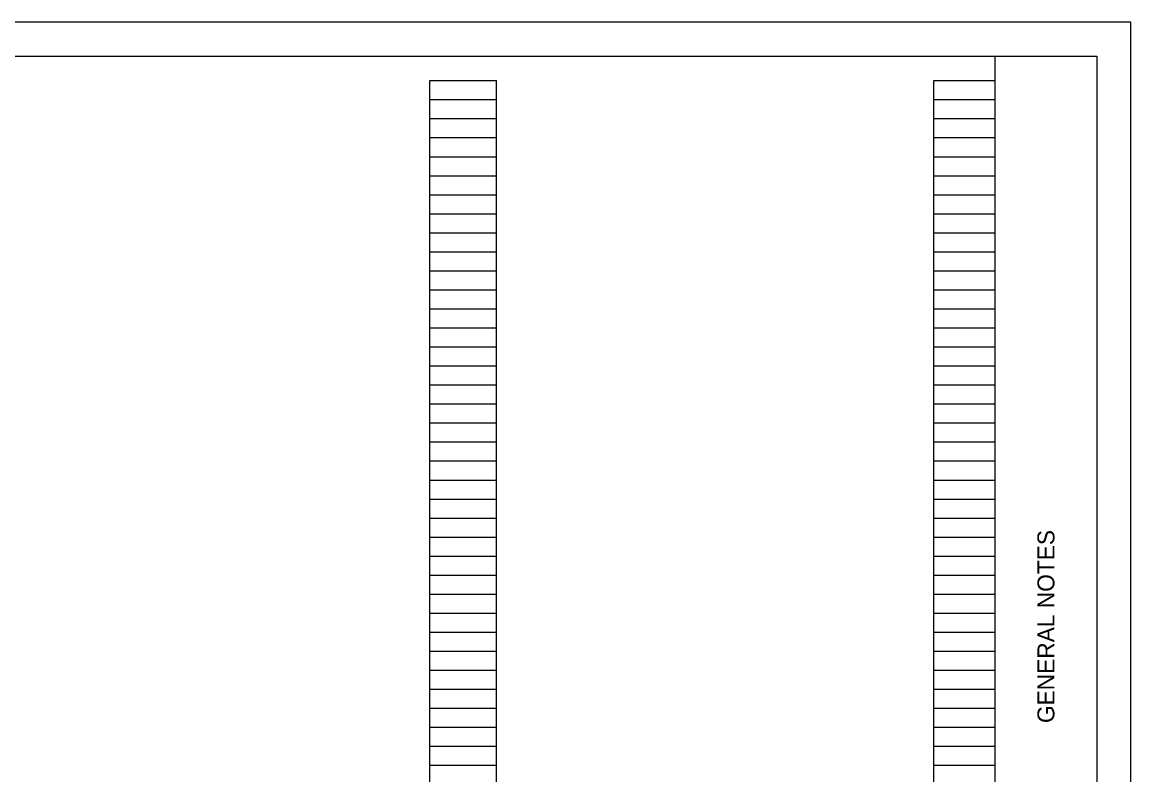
# Model space of a CAD drawing. Extents: x -9.5 to 34, y -6.8 to 28.4.
# Drawn here: x 17.67 to 34, y 10.92 to 22 of the extents above; entities that cross this region are included whole.
import ezdxf

# ---------------------------------------------------------------- set-up
doc = ezdxf.new("R2010")
doc.units = 0
for name, color, linetype in [('PV_P_Drive', 7, 'Continuous'), ('SH_Border', 7, 'Continuous'), ('SH_Cut_Line', 7, 'Continuous'), ('SH_Data', 7, 'Continuous')]:
    doc.layers.add(name, color=color, linetype=linetype)

msp = doc.modelspace()

# ---------------------------------------------------------------- linework, layer by layer
at = {"layer": 'PV_P_Drive'}
for p, q in [((23.68, 0.98), (23.68, 21.14)), ((23.68, 21.14), (24.66, 21.14)), ((24.66, 0.98), (24.66, 21.14)), ((31.1, 0.98), (31.1, 21.14)), ((31.1, 21.14), (32, 21.14)), ((32, 0.98), (32, 21.14)), ((23.68, 20.86), (24.66, 20.86)), ((31.1, 20.86), (32, 20.86)), ((23.68, 20.58), (24.66, 20.58)), ((31.1, 20.58), (32, 20.58)), ((23.68, 20.3), (24.66, 20.3)), ((31.1, 20.3), (32, 20.3)), ((23.68, 20.02), (24.66, 20.02)), ((31.1, 20.02), (32, 20.02)), ((23.68, 19.74), (24.66, 19.74)), ((31.1, 19.74), (32, 19.74)), ((23.68, 19.46), (24.66, 19.46)), ((31.1, 19.46), (32, 19.46)), ((23.68, 19.18), (24.66, 19.18)), ((31.1, 19.18), (32, 19.18)), ((23.68, 18.9), (24.66, 18.9)), ((31.1, 18.9), (32, 18.9)), ((23.68, 18.62), (24.66, 18.62)), ((31.1, 18.62), (32, 18.62)), ((23.68, 18.34), (24.66, 18.34)), ((31.1, 18.34), (32, 18.34)), ((23.68, 18.06), (24.66, 18.06)), ((31.1, 18.06), (32, 18.06)), ((23.68, 17.78), (24.66, 17.78)), ((31.1, 17.78), (32, 17.78)), ((23.68, 17.5), (24.66, 17.5)), ((31.1, 17.5), (32, 17.5)), ((23.68, 17.22), (24.66, 17.22)), ((31.1, 17.22), (32, 17.22)), ((23.68, 16.94), (24.66, 16.94)), ((31.1, 16.94), (32, 16.94)), ((23.68, 16.66), (24.66, 16.66)), ((31.1, 16.66), (32, 16.66)), ((23.68, 16.38), (24.66, 16.38)), ((31.1, 16.38), (32, 16.38)), ((23.68, 16.1), (24.66, 16.1)), ((31.1, 16.1), (32, 16.1)), ((23.68, 15.82), (24.66, 15.82)), ((31.1, 15.82), (32, 15.82)), ((23.68, 15.54), (24.66, 15.54)), ((31.1, 15.54), (32, 15.54)), ((23.68, 15.26), (24.66, 15.26)), ((31.1, 15.26), (32, 15.26)), ((23.68, 14.98), (24.66, 14.98)), ((31.1, 14.98), (32, 14.98)), ((23.68, 14.7), (24.66, 14.7)), ((31.1, 14.7), (32, 14.7)), ((23.68, 14.42), (24.66, 14.42)), ((31.1, 14.42), (32, 14.42)), ((23.68, 14.14), (24.66, 14.14)), ((31.1, 14.14), (32, 14.14)), ((23.68, 13.86), (24.66, 13.86)), ((31.1, 13.86), (32, 13.86)), ((23.68, 13.58), (24.66, 13.58)), ((31.1, 13.58), (32, 13.58)), ((23.68, 13.3), (24.66, 13.3)), ((31.1, 13.3), (32, 13.3)), ((23.68, 13.02), (24.66, 13.02)), ((31.1, 13.02), (32, 13.02)), ((23.68, 12.74), (24.66, 12.74)), ((31.1, 12.74), (32, 12.74)), ((23.68, 12.46), (24.66, 12.46)), ((31.1, 12.46), (32, 12.46)), ((23.68, 12.18), (24.66, 12.18)), ((31.1, 12.18), (32, 12.18)), ((23.68, 11.9), (24.66, 11.9)), ((31.1, 11.9), (32, 11.9)), ((23.68, 11.62), (24.66, 11.62)), ((31.1, 11.62), (32, 11.62)), ((23.68, 11.34), (24.66, 11.34)), ((31.1, 11.34), (32, 11.34)), ((23.68, 11.06), (24.66, 11.06)), ((31.1, 11.06), (32, 11.06))]:
    msp.add_line(p, q, dxfattribs=at)
at = {"layer": 'SH_Border'}
msp.add_lwpolyline([(0, 0), (34, 0), (34, 22), (0, 22)], close=True, dxfattribs=at)
at = {"layer": 'SH_Cut_Line'}
msp.add_line((32, 0.5), (32, 21.5), dxfattribs=at)
msp.add_lwpolyline([(1.5, 21.5), (33.5, 21.5), (33.5, 0.5), (1.5, 0.5)], close=True, dxfattribs=at)

# ---------------------------------------------------------------- texts
at = {"layer": 'SH_Data'}
msp.add_text('GENERAL NOTES', height=0.25, rotation=90, dxfattribs=at).set_placement((32.875, 11.682))

doc.saveas('drawing.dxf')
